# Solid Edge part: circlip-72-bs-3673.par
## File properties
Title: External circlip for shaft Ø72 - BS 3673
Author: TraceParts S.A.
Template: Iso Metric Part.par
Last saved by: Nimesh.N
Revision: 4
Application: TraceParts
Company: TraceParts S.A.
Density: 7833.000 kg/m^3
Accuracy: 0.990
REFERENCE: BS 3673 - d 72 - d2 69
STANDARD: BS 3673
DESIGN: External circlip for shaft Ø72 - BS 3673
OMNICLASS23: 23.13.23.11.13.25
TraceParts.PartNumber: 10-08012002-076217
TraceParts.PartVersion: 1.3.0
TraceParts.InstanceId: 10-08012002-0762179ZHTVLQ7FBO9WATPHBC2H8987
TraceParts.PartStandardAcronym: BS
TraceParts.PartTitle: External circlip
TRACEPARTS: TRACEPARTS
TraceParts.PartLanguage: en
Username: Nimesh.N
Material: Steel
Face Style: Bronze (aged)
Fill Style: ANSI32(Steel)
Virtual Style: ANSI32(Steel)
Grouping: Metals\Steel
LibraryName: Materials
Coef. of Thermal Exp: 1.3e-05
Thermal Conductivity: 32.0
Specific Heat: 481.0
Modulus of Elasticity: 199947953000.0
Poisson's Ratio: 0.29
Yield Stress: 262000766.0
Ultimate Stress: 358527364.0
Elongation: 0.0
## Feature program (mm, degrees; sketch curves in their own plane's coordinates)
body "unnamed Body 1"
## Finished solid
Body 1: solid body, 16 faces, 40 edges, 28 vertices.
  Faces by surface: cylinder 8, plane 8
  Edges by curve: line 24, circle 16
Bounding box of the edges (mm): 78.067 x 84.010 x 2.500, from (-39.0333, -42.71, 0) to (39.0333, 41.3, 2.5).
Cylindrical faces by radius (mm): R1.5 x2, R4.2227 x4, R34.5 x1, R39.0333 x1
Planar faces by outward normal: +x 2, +z 1, -x 2, -y 2, -z 1
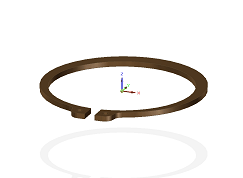
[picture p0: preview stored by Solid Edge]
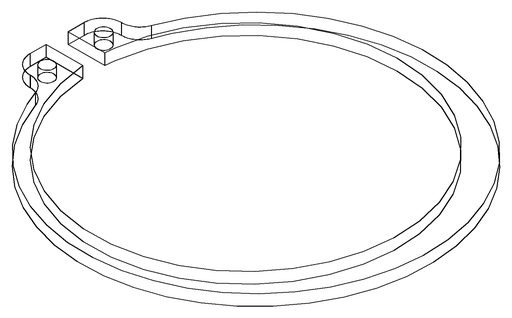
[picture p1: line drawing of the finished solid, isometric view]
